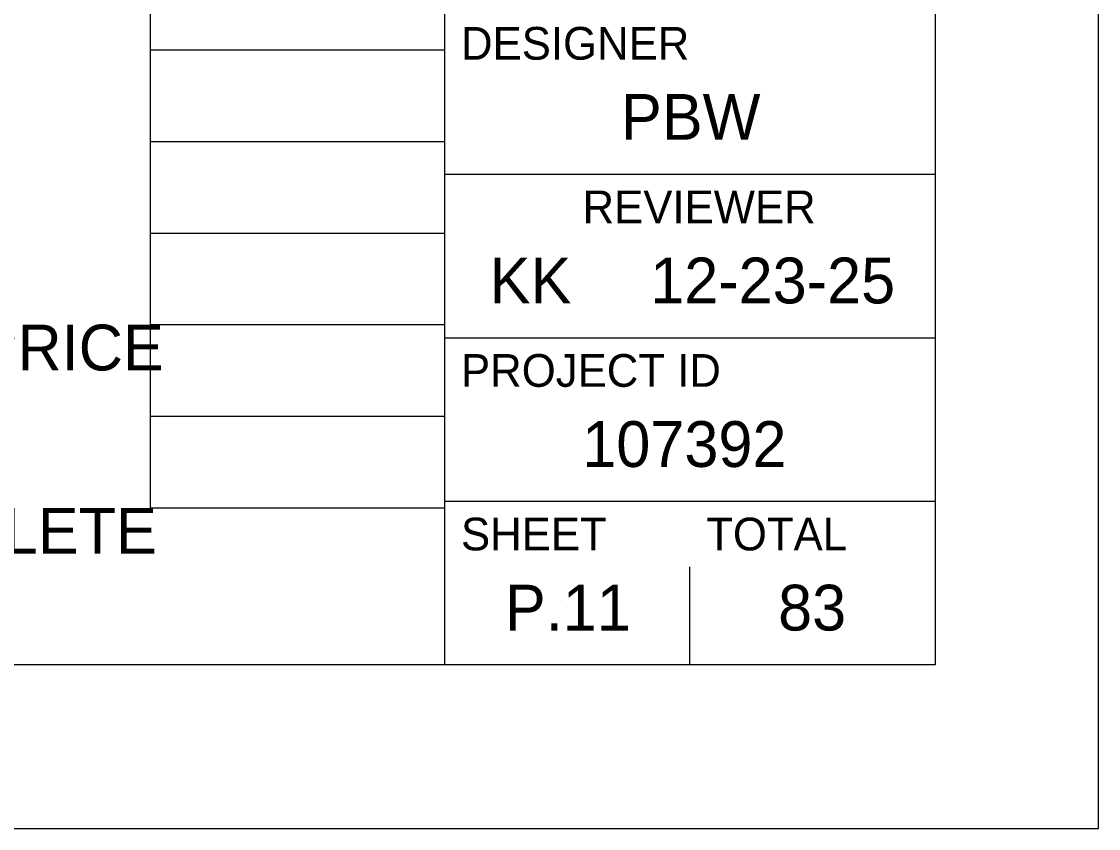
# Model space of a CAD drawing. Extents: x -50 to 112, y -27 to 22.
# Drawn here: x 69.706 to 73, y 0 to 2.467 of the extents above; entities that cross this region are included whole.
import ezdxf

# ---------------------------------------------------------------- set-up
doc = ezdxf.new("R2010")
doc.units = 0
for name, color, linetype in [('SC_Scratch1', 7, 'Continuous'), ('SH_Border', 7, 'Continuous'), ('SH_Cut_Line', 7, 'Continuous'), ('SH_Data', 7, 'Continuous'), ('SH_Text', 7, 'Continuous')]:
    doc.layers.add(name, color=color, linetype=linetype)

msp = doc.modelspace()

# ---------------------------------------------------------------- linework, layer by layer
at = {"layer": 'SC_Scratch1'}
for p, q in [((70.1, 0.98), (70.1, 21.14)), ((71, 0.98), (71, 21.14)), ((70.1, 2.38), (71, 2.38)), ((70.1, 2.1), (71, 2.1)), ((70.1, 1.82), (71, 1.82)), ((70.1, 1.54), (71, 1.54)), ((70.1, 1.26), (71, 1.26)), ((70.1, 0.98), (71, 0.98))]:
    msp.add_line(p, q, dxfattribs=at)
at = {"layer": 'SH_Border'}
for p, q in [((71, 0.5), (71, 21.5)), ((71, 2), (72.5, 2)), ((71, 1.5), (72.5, 1.5)), ((71, 1), (72.5, 1))]:
    msp.add_line(p, q, dxfattribs=at)
msp.add_lwpolyline([(40.5, 21.5), (72.5, 21.5), (72.5, 0.5), (40.5, 0.5)], close=True, dxfattribs=at)
at = {"layer": 'SH_Cut_Line'}
msp.add_lwpolyline([(39, 0), (73, 0), (73, 22), (39, 22)], close=True, dxfattribs=at)
at = {"layer": 'SH_Data'}
for p, q in [((71.75, 0.5), (71.75, 0.8)), ((71.375, 0.675), (71.375, 0.675))]:
    msp.add_line(p, q, dxfattribs=at)

# ---------------------------------------------------------------- texts
for s, height, p in [('DESIGNER', 0.1, (71.05, 2.35)), ('PBW', 0.14, (71.5395, 2.105)), ('REVIEWER', 0.1, (71.4218, 1.85)), ('12-23-25', 0.14, (71.6287, 1.605)), ('KK', 0.14, (71.1379, 1.605)), ('PROJECT ID', 0.1, (71.05, 1.35)), ('107392', 0.14, (71.4209, 1.105)), ('SHEET', 0.1, (71.05, 0.85)), ('TOTAL', 0.1, (71.8, 0.85)), ('P.11', 0.14, (71.1844, 0.605)), ('83', 0.14, (72.02, 0.605))]:
    msp.add_text(s, height=height, dxfattribs=at).set_placement(p)
at = {"layer": 'SH_Text'}
for s, p in [('PAYMENT FOR THE ABOVE WORK SHALL BE MADE AT THE UNIT PRICE ', (63.66, 1.4)), ('MATERIALS NECESSARY TO CONSTRUCT AND MAINTAIN A COMPLETE ', (63.66, 0.84))]:
    msp.add_text(s, height=0.14, dxfattribs=at).set_placement(p)

doc.saveas('drawing.dxf')
